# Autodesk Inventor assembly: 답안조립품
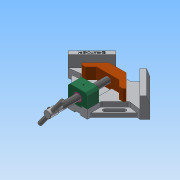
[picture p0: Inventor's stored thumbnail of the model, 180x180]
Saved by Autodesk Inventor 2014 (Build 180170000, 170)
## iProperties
Created: 2020-05
Part Number: 답안조립품
Document SubType Name: Assembly
Designer: net
Author: net
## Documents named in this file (11)
- C:\Users\net\Desktop\700506V1045\답안조립품.iam
- C:\Users\net\Desktop\700506V1045\본체.ipt
- C:\Users\net\Desktop\700506V1045\조.ipt
- C:\Users\net\Desktop\700506V1045\서포트.ipt
- C:\Users\net\Desktop\700506V1045\부시.ipt
- C:\Users\net\Desktop\700506V1045\리드스크류.ipt
- C:\Users\net\Desktop\700506V1045\멈춤나사 M4x10.ipt
- C:\Users\net\Desktop\700506V1045\핸들.ipt
- C:\Users\net\Desktop\700506V1045\멈춤나사 M4x5.ipt
- C:\Users\net\Desktop\700506V1045\평행 핀 2.5x24.ipt
- C:\Users\net\Desktop\700506V1045\볼트 M4x16.ipt
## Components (1 placed, 1 different names)
1. 핸들:1
